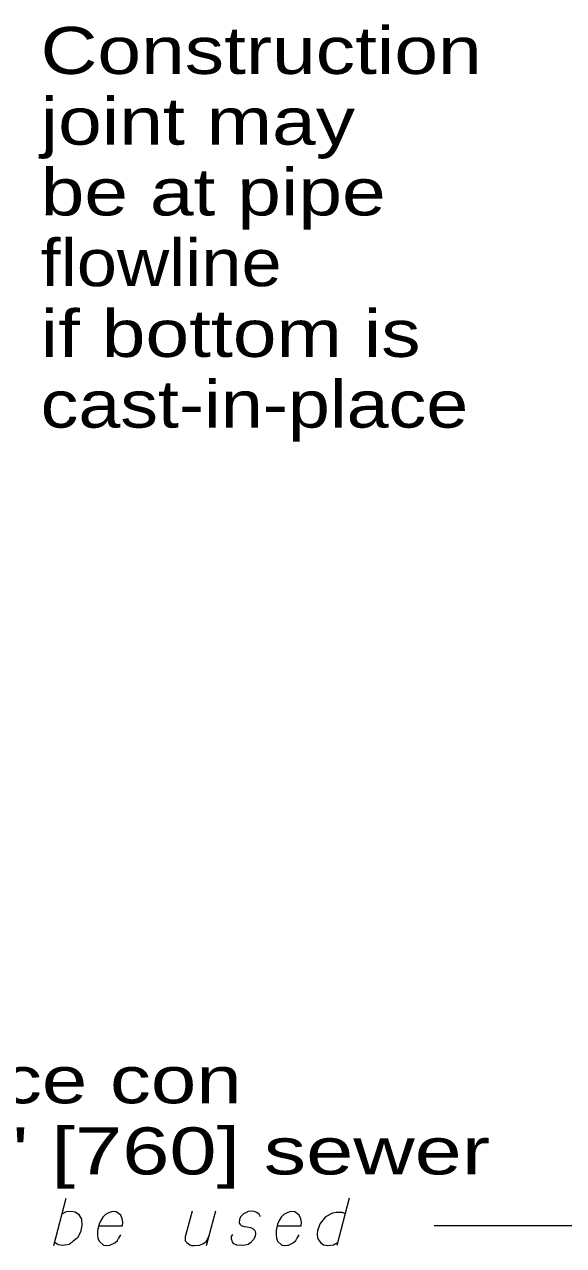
# Model space of a CAD drawing. Extents: x 1083.1 to 1117.1, y 697.4 to 741.4.
# Drawn here: x 1094.348 to 1096.137, y 727.903 to 731.954 of the extents above; entities that cross this region are included whole.
import ezdxf

# ---------------------------------------------------------------- set-up
doc = ezdxf.new("R2010")
doc.units = 0
doc.header["$LTSCALE"] = 0.062
doc.layers.add('1', color=7, linetype='Continuous', lineweight=13)

msp = doc.modelspace()

# ---------------------------------------------------------------- linework, layer by layer
at = {"layer": '1'}
for p, q in [((1094.446, 727.90325), (1094.48683, 728.06058)), ((1095.42592, 728.06058), (1095.385, 727.90325)), ((1094.95267, 727.90325), (1094.98367, 728.0185))]:
    msp.add_line(p, q, dxfattribs=at)
for points in [[(1098.12467, 729.49692), (1097.59092, 727.9685), (1095.70825, 727.9685)], [(1094.47325, 728.00858), (1094.48808, 728.016), (1094.50425, 728.01725), (1094.51658, 728.01475), (1094.52775, 728.00733), (1094.53767, 727.99125), (1094.53892, 727.97017), (1094.53392, 727.94792), (1094.524, 727.92933), (1094.49675, 727.907), (1094.47575, 727.90325), (1094.45958, 727.90575), (1094.4485, 727.91317)], [(1094.59467, 727.96892), (1094.67392, 727.96892), (1094.67517, 727.98133), (1094.67267, 727.9925), (1094.66775, 728.00367), (1094.65292, 728.01475), (1094.6405, 728.016), (1094.63058, 728.0135), (1094.61692, 728.00608), (1094.60825, 727.99742), (1094.60083, 727.98383), (1094.59592, 727.97392), (1094.59092, 727.95283), (1094.59092, 727.93925), (1094.59217, 727.92808), (1094.59592, 727.91817), (1094.61075, 727.9045), (1094.62067, 727.90325), (1094.63058, 727.9045), (1094.63183, 727.9045), (1094.64792, 727.91192), (1094.65658, 727.92058), (1094.66033, 727.92683), (1094.66158, 727.92808), (1094.66775, 727.93925)], [(1094.90433, 728.01725), (1094.88208, 727.93175), (1094.88208, 727.91942), (1094.88825, 727.91192), (1094.89692, 727.90575), (1094.90317, 727.90325), (1094.91183, 727.90325), (1094.92917, 727.9045), (1094.94033, 727.9095), (1094.95142, 727.91692), (1094.96133, 727.9355)], [(1095.13108, 727.99867), (1095.12733, 728.00733), (1095.11867, 728.0135), (1095.11125, 728.016), (1095.10008, 728.01725), (1095.09017, 728.016), (1095.07533, 728.00858), (1095.06542, 727.99867), (1095.06167, 727.99), (1095.0605, 727.98008), (1095.06292, 727.97392), (1095.06792, 727.97017), (1095.07033, 727.96892), (1095.07783, 727.9665), (1095.0865, 727.96525), (1095.09883, 727.96275), (1095.10633, 727.96025), (1095.1125, 727.95283), (1095.115, 727.94417), (1095.11375, 727.933), (1095.10875, 727.92308), (1095.09883, 727.91192), (1095.09017, 727.907), (1095.08025, 727.9045), (1095.06792, 727.90325), (1095.053, 727.9045), (1095.04308, 727.9095), (1095.03817, 727.91567), (1095.03567, 727.92433), (1095.03567, 727.933), (1095.03942, 727.94042)], [(1095.18683, 727.96892), (1095.26608, 727.96892), (1095.26733, 727.98133), (1095.26492, 727.9925), (1095.25992, 728.00367), (1095.24508, 728.01475), (1095.23267, 728.016), (1095.22275, 728.0135), (1095.20917, 728.00608), (1095.2005, 727.99742), (1095.193, 727.98383), (1095.18808, 727.97392), (1095.18308, 727.95283), (1095.18308, 727.93925), (1095.18433, 727.92808), (1095.18808, 727.91817), (1095.20292, 727.9045), (1095.21283, 727.90325), (1095.22275, 727.9045), (1095.224, 727.9045), (1095.24008, 727.91192), (1095.24875, 727.92058), (1095.2525, 727.92683), (1095.25375, 727.92808), (1095.25992, 727.93925)], [(1095.41233, 728.00858), (1095.40358, 728.0135), (1095.38258, 728.0135), (1095.37017, 728.01108), (1095.34783, 727.99867), (1095.32933, 727.97633), (1095.32058, 727.95283), (1095.31942, 727.94042), (1095.32058, 727.9305), (1095.32433, 727.92183), (1095.33175, 727.91192), (1095.34042, 727.90575), (1095.35408, 727.90325), (1095.364, 727.9045), (1095.37392, 727.90575), (1095.3875, 727.91317)]]:
    msp.add_lwpolyline(points, dxfattribs=at)

# ---------------------------------------------------------------- texts
for s, width, p in [('Construction', 1.25, (1094.40192, 731.79)), ('joint may', 1.25, (1094.40192, 731.55533)), ('be at pipe', 1.25, (1094.40192, 731.32067)), ('flowline', 1.15, (1094.40192, 731.086)), ('if bottom is', 1.25, (1094.40192, 730.85133)), ('cast-in-place', 1.2, (1094.40192, 730.61667)), ('Precast or cast-in-place con', 1.3, (1091.70817, 728.37525)), ('crete.  Bottom for 30" [760] sewer', 1.35, (1091.70817, 728.13925))]:
    msp.add_text(s, height=0.156, dxfattribs=dict(at, width=width)).set_placement(p)

doc.saveas('drawing.dxf')
